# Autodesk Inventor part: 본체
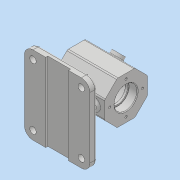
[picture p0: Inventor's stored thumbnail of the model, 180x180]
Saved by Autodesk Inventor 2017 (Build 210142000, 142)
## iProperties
Part Number: 본체
Material: 일반
Document SubType Name: Modeling
Designer: MRC
Density: 1 g/cm^3
Appearance: 기본값
Author: MRC
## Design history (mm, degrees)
sketch "스케치1"
  geometry: L1 (-35, 40)-(35, 40); L2 (35, 40)-(35, 16); L3 (35, 16)-(23, 16); L4 (23, 16)-(23, 14); L5 (23, 14)-(20, 14); L6 (20, 14)-(20, 25); L7 (20, 25)-(-20, 25); L8 (-20, 25)-(-20, 14); L9 (-20, 14)-(-23, 14); L10 (-23, 14)-(-23, 16); L11 (-23, 16)-(-35, 16); L12 (-35, 16)-(-35, 40); L13 (-35, 0)-(35, 0); 3 further points
  constraints: 26 end point, 10 perpendicular, 5 point on line, 3 midpoint, 2 vertical alignment, 1 horizontal
  dimensions: "d0" = 35 distance from line of point (0, 0) L12; "d1" = 35 distance from line of point (0, 0) L2; "d2" = 12 distance of L10.end L11.end; "d4" = 40 distance of L6.end L7.end; "d5" = 12 distance of L2.end L3.end; "d6" = 32 diameter of L11 L13; "d7" = 28 diameter of L9 L13; "d8" = 80 diameter of L1 L13; "d9" = 50 diameter of L7 L13
revolve "회전1" sketch "스케치1" stored, may be unused: angle "d10" = 90 deg
sketch "스케치2"
  geometry: L1 (30, 12.426)-(30, -12.426); L2 (30, -12.426)-(12.426, -30); L3 (12.426, -30)-(-12.426, -30); L4 (-12.426, -30)-(-30, -12.426); L5 (-30, -12.426)-(-30, 12.426); L6 (-30, 12.426)-(-12.426, 30); L7 (-12.426, 30)-(12.426, 30); L8 (12.426, 30)-(30, 12.426); 2 further points
  constraints: 16 end point, 1 coincident, 1 horizontal, 17 other
  dimensions: "d62" = 60 distance between parallel lines of L3 L7
extrude "돌출1" sketch "스케치2" stored distance "d12" = 0; taper "d13" = 0 deg
sketch "스케치4"
  geometry: L1 (-52, -55)-(-62, -55); L2 (-62, -55)-(-62, 55); L3 (-62, 55)-(-52, 55); L4 (-52, 55)-(-52, -55); 2 further points
  constraints: 8 end point, 2 parallel, 1 horizontal, 1 horizontal alignment, 1 midpoint, 1 perpendicular
  dimensions: "d26" = 62 distance from line of point (0, 0) L2; "d27" = 10 distance of L2.end L3.end; "d28" = 110 distance of L1.end L2.end
extrude "돌출2" join sketch "스케치4" stored distance "d29" = 92; taper "d30" = 0 deg
sketch "스케치5"
  geometry: L1 (26, 55)-(66, 55); L2 (26, 61)-(66, 61); L3 (66, 49)-(26, 49); A1 r 6 centre (26, 55) between (26, 61) and (26, 49); A2 r 6 centre (66, 55) between (66, 49) and (66, 61); 2 further points
  constraints: 8 end point, 4 point on circle, 4 tangent, 2 centre point, 1 coincident, 1 horizontal, 1 midpoint, 1 parallel
  dimensions: "d32" = 12 distance between parallel lines of L3 L2; "d97" = 40 distance of L1.start L1.end
extrude "돌출3" join sketch "스케치5" stored distance "d33" = 92; taper "d34" = 0 deg
fillet "모깎기1" dims "d35" = 12
sketch "스케치6"
  geometry: L1 (80, -98)-(80, -12) reference; L2 (68, -110)-(0, -110) reference; L3 (-12, -12)-(-12, -98) reference; L4 (68, 0)-(0, 0) reference; A1 r 12 centre (68, -12) between (80, -12) and (68, 0) reference; A2 r 12 centre (68, -98) between (68, -110) and (80, -98) reference; A3 r 12 centre (0, -98) between (-12, -98) and (0, -110) reference; A4 r 12 centre (0, -12) between (0, 0) and (-12, -12) reference; 5 further points
  constraints: 4 coincident
hole "구멍2" sketch "스케치6" at (0, -12), (68, -12), (68, -98), (0, -98) diameter "d36" = 9; stored, may be unused: countersink angle "d40" = 90 deg, drill point angle "d42" = 118 deg; dims "d37" = 8, "d38" = 4, "d39" = 2, "d41" = 10
sketch "스케치7"
  geometry: L1 (68, -10)-(0, -10) reference; L2 (18, -7)-(50, -7); L3 (50, -7)-(50, -10); L4 (50, -10)-(18, -10); L5 (18, -10)-(18, -7); L6 (18, -7)-(50, -10); L7 (50, -7)-(18, -10); 3 further points
  constraints: 12 end point, 3 midpoint, 2 parallel, 1 horizontal, 1 perpendicular, 1 point on line, 1 vertical alignment
  dimensions: "d43" = 32 distance of L2.start L2.end; "d44" = 3 distance of L2.end L3.end
extrude "돌출4" cut sketch "스케치7" stored distance "d45" = 92; taper "d46" = 0 deg
sketch "스케치11"
  geometry: 2 further points
  constraints: 1 vertical alignment
  dimensions: "d63" = 23 distance of point (30, 12.426) point (30, 35.426)
hole "구멍4" sketch "스케치11" at (30, 35.426) diameter "d64" = 3.242; stored, may be unused: countersink angle "d68" = 90 deg, drill point angle "d70" = 118 deg; dims "d65" = 8, "d66" = 4, "d67" = 2, "d69" = 10
sketch "스케치12"
  geometry: C1 r 8 at (35, -12.426); 1 further point
  constraints: 1 centre point, 1 coincident
  dimensions: "d74" = 16 diameter of C1
extrude "돌출6" join sketch "스케치12" distance "d75" = 5; taper "d76" = 0 deg
hole "구멍5" diameter "d79" = 8; stored, may be unused: countersink angle "d83" = 90 deg, drill point angle "d85" = 118 deg; dims "d77" = 10, "d78" = 10, "d80" = 8, "d81" = 4, "d82" = 2, "d84" = 18
sketch "스케치13"
  geometry: L1 (0, 42.426)-(0, 24.853) reference; L2 (0, 42.426)-(70, 42.426) reference; 2 further points
  constraints: 1 other
  dimensions: "d86" = 35 distance from line of L1 point (35, 12.426); "d87" = 30 distance from line of L2 point (35, 12.426)
feature "엠보싱1" sketch "스케치13" dims "d0" = 35, "d1" = 35, "d2" = 12, "d4" = 40, "d5" = 12, "d6" = 32, "d7" = 28, "d8" = 80, "d9" = 50, "d88" = 0.5, "d89" = 0
fillet "모깎기2" dims "d90" = 3
fillet "모깎기3" dims "d91" = 3
fillet "모깎기4" dims "d92" = 0.3
chamfer "모따기1" distance "d93" = 1; stored, may be unused: second distance "d94" = 2, angle "d95" = 45 deg
fillet "모깎기5" dims "d96" = 1
fillet "모깎기6" dims "d98" = 1
node "솔리드1"
pattern_circular "원형 패턴2" dims angle "d72" = 360 deg
mirror "미러2"
node "투영된 루프1"
